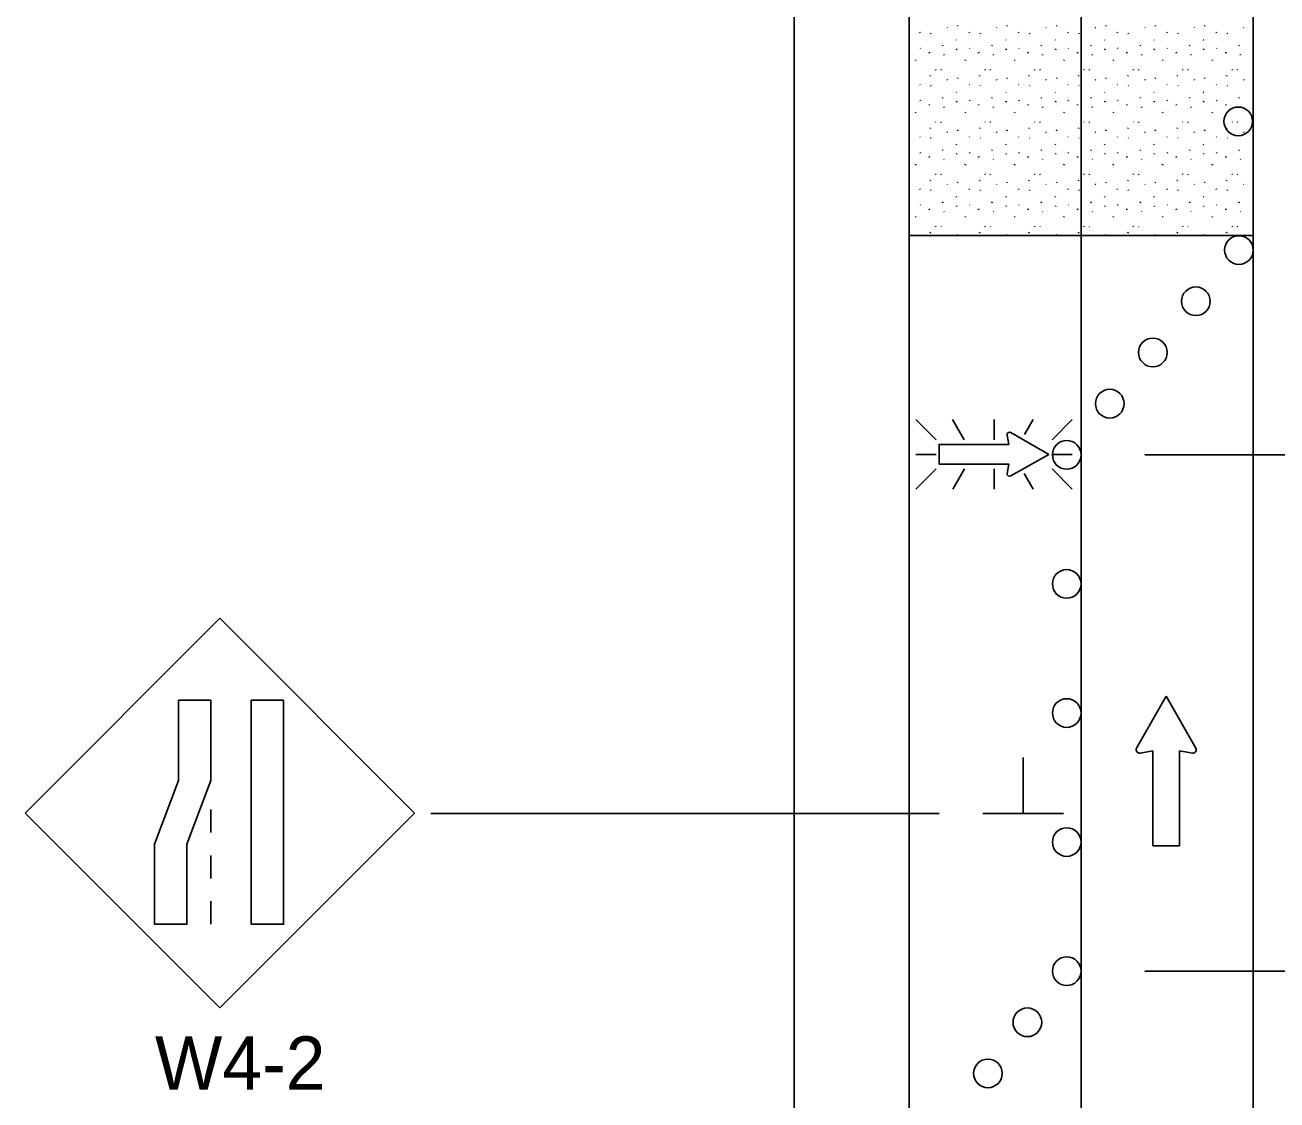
# Model space of a CAD drawing. Extents: x 16794 to 19504, y 7009 to 8243.
# Drawn here: x 17909.1 to 18083.7, y 7860.1 to 8010 of the extents above; entities that cross this region are included whole.
import ezdxf

# ---------------------------------------------------------------- set-up
doc = ezdxf.new("R2010")
doc.units = 0
for name, color, linetype in [('ALI_LEGAL_EX', 7, 'Continuous'), ('MT_SCRATCH_LEVEL_A', 7, 'Continuous'), ('MT_SCRATCH_LEVEL_E', 7, 'Continuous'), ('PAVT_EDGE_EX', 7, 'Continuous'), ('TRAFFIC_SIGNS_PR', 7, 'Continuous'), ('TYPICAL_TEXT_DIMEN_PR', 7, 'Continuous')]:
    doc.layers.add(name, color=color, linetype=linetype)

msp = doc.modelspace()

# ---------------------------------------------------------------- linework, layer by layer
at = {"layer": 'ALI_LEGAL_EX'}
for p, q in [((18056.37, 8191.42), (18056.37, 7362.23)), ((18080.37, 8191.42), (18080.37, 7362.23)), ((18080.37, 8191.42), (18080.37, 7362.23))]:
    msp.add_line(p, q, dxfattribs=at)
for points in [[(18056.37, 7991.42), (18056.37, 7966.42)], [(18080.37, 7991.42), (18080.37, 7980.06)], [(18056.37, 7891.42), (18056.37, 7880.22)], [(18080.37, 7891.42), (18080.37, 7866.42)]]:
    msp.add_lwpolyline(points, dxfattribs=at)
at = {"layer": 'MT_SCRATCH_LEVEL_A'}
msp.add_line((18080.37, 7980.62), (18032.37, 7980.62), dxfattribs=at)
at = {"layer": 'MT_SCRATCH_LEVEL_E'}
for p, q in [((18068.21, 7916.38), (18064.1, 7909.14)), ((18072.36, 7909.14), (18068.21, 7916.38)), ((18064.58, 7908.46), (18066.36, 7908.77)), ((18066.36, 7908.77), (18066.36, 7895.52)), ((18070.1, 7895.52), (18070.1, 7908.77)), ((18070.1, 7908.77), (18071.88, 7908.46)), ((18066.36, 7895.52), (18070.1, 7895.52))]:
    msp.add_line(p, q, dxfattribs=at)
for centre, start, end in [((18064.51, 7908.92), 150.4248, 279.9638), ((18071.95, 7908.92), 260.0362, 29.7731)]:
    msp.add_arc(centre, 0.463, start, end, dxfattribs=at)
at = {"layer": 'PAVT_EDGE_EX'}
for p, q in [((18016.37, 8214.7), (18016.37, 7554.34)), ((18032.37, 8214.7), (18032.37, 7554.34)), ((18032.37, 8010.04), (18032.37, 7980.62)), ((18037.68, 8009.67), (18037.73, 8009.59)), ((18039.13, 8009.82), (18039.18, 8009.94)), ((18044.57, 8009.67), (18044.62, 8009.59)), ((18046.02, 8009.82), (18046.07, 8009.94)), ((18051.46, 8009.67), (18051.51, 8009.59)), ((18052.91, 8009.82), (18052.96, 8009.94)), ((18058.34, 8009.67), (18058.4, 8009.59)), ((18059.79, 8009.82), (18059.85, 8009.94)), ((18065.23, 8009.67), (18065.28, 8009.59)), ((18066.68, 8009.82), (18066.73, 8009.94)), ((18072.12, 8009.67), (18072.17, 8009.59)), ((18073.57, 8009.82), (18073.62, 8009.94)), ((18079.01, 8009.67), (18079.06, 8009.59)), ((18033.86, 8008.99), (18033.91, 8008.92)), ((18035.39, 8008.85), (18035.44, 8008.78)), ((18038.96, 8007.93), (18039.01, 8007.86)), ((18040.75, 8008.99), (18040.8, 8008.92)), ((18042.28, 8008.85), (18042.33, 8008.78)), ((18045.85, 8007.93), (18045.9, 8007.86)), ((18047.64, 8008.99), (18047.69, 8008.92)), ((18049.17, 8008.85), (18049.22, 8008.78)), ((18052.73, 8007.93), (18052.79, 8007.86)), ((18054.53, 8008.99), (18054.58, 8008.92)), ((18056.06, 8008.85), (18056.11, 8008.78)), ((18059.62, 8007.93), (18059.67, 8007.86)), ((18061.41, 8008.99), (18061.46, 8008.92)), ((18062.94, 8008.85), (18062.99, 8008.78)), ((18066.51, 8007.93), (18066.56, 8007.86)), ((18068.3, 8008.99), (18068.35, 8008.92)), ((18069.83, 8008.85), (18069.88, 8008.78)), ((18073.4, 8007.93), (18073.45, 8007.86)), ((18075.19, 8008.99), (18075.24, 8008.92)), ((18076.72, 8008.85), (18076.77, 8008.78)), ((18080.28, 8007.93), (18080.34, 8007.86)), ((18033.91, 8006.78), (18033.96, 8006.71)), ((18035.19, 8006.21), (18035.21, 8006.09)), ((18037.03, 8007.07), (18037.08, 8007.18)), ((18037.22, 8005.86), (18037.27, 8005.79)), ((18039, 8006.53), (18039.05, 8006.65)), ((18040.8, 8006.78), (18040.85, 8006.71)), ((18042.08, 8006.21), (18042.09, 8006.09)), ((18043.92, 8007.07), (18043.97, 8007.18)), ((18044.11, 8005.86), (18044.16, 8005.79)), ((18045.89, 8006.53), (18045.94, 8006.65)), ((18047.69, 8006.78), (18047.74, 8006.71)), ((18048.97, 8006.21), (18048.98, 8006.09)), ((18050.81, 8007.07), (18050.86, 8007.18)), ((18051, 8005.86), (18051.05, 8005.79)), ((18052.78, 8006.53), (18052.83, 8006.65)), ((18054.57, 8006.78), (18054.62, 8006.71)), ((18055.85, 8006.21), (18055.87, 8006.09)), ((18057.7, 8007.07), (18057.75, 8007.18)), ((18057.89, 8005.86), (18057.94, 8005.79)), ((18059.66, 8006.53), (18059.72, 8006.65)), ((18061.46, 8006.78), (18061.51, 8006.71)), ((18062.74, 8006.21), (18062.76, 8006.09)), ((18064.58, 8007.07), (18064.64, 8007.18)), ((18064.77, 8005.86), (18064.82, 8005.79)), ((18066.55, 8006.53), (18066.6, 8006.65)), ((18068.35, 8006.78), (18068.4, 8006.71)), ((18069.63, 8006.21), (18069.64, 8006.09)), ((18071.47, 8007.07), (18071.52, 8007.18)), ((18071.66, 8005.86), (18071.71, 8005.79)), ((18073.44, 8006.53), (18073.49, 8006.65)), ((18075.24, 8006.78), (18075.29, 8006.71)), ((18076.52, 8006.21), (18076.53, 8006.09)), ((18078.36, 8007.07), (18078.41, 8007.18)), ((18078.55, 8005.86), (18078.6, 8005.79)), ((18080.33, 8006.53), (18080.37, 8006.62)), ((18033.29, 8005.03), (18033.34, 8005.15)), ((18040.18, 8005.03), (18040.23, 8005.15)), ((18047.07, 8005.03), (18047.12, 8005.15)), ((18053.96, 8005.03), (18054.01, 8005.15)), ((18060.84, 8005.03), (18060.89, 8005.15)), ((18067.73, 8005.03), (18067.78, 8005.15)), ((18074.62, 8005.03), (18074.67, 8005.15)), ((18035.31, 8002.84), (18035.36, 8002.95)), ((18036.08, 8003.8), (18036.13, 8003.72)), ((18036.81, 8003.77), (18036.87, 8003.69)), ((18037.68, 8002.39), (18037.73, 8002.31)), ((18039.13, 8002.54), (18039.18, 8002.65)), ((18042.2, 8002.84), (18042.25, 8002.95)), ((18042.96, 8003.8), (18043.01, 8003.72)), ((18043.7, 8003.77), (18043.75, 8003.69)), ((18044.57, 8002.39), (18044.62, 8002.31)), ((18046.02, 8002.54), (18046.07, 8002.65)), ((18049.09, 8002.84), (18049.14, 8002.95)), ((18049.85, 8003.8), (18049.9, 8003.72)), ((18050.59, 8003.77), (18050.64, 8003.69)), ((18051.46, 8002.39), (18051.51, 8002.31)), ((18052.91, 8002.54), (18052.96, 8002.65)), ((18055.98, 8002.84), (18056.03, 8002.95)), ((18056.74, 8003.8), (18056.79, 8003.72)), ((18057.48, 8003.77), (18057.53, 8003.69)), ((18058.34, 8002.39), (18058.4, 8002.31)), ((18059.79, 8002.54), (18059.85, 8002.65)), ((18062.86, 8002.84), (18062.91, 8002.95)), ((18063.63, 8003.8), (18063.68, 8003.72)), ((18064.36, 8003.77), (18064.42, 8003.69)), ((18065.23, 8002.39), (18065.28, 8002.31)), ((18066.68, 8002.54), (18066.73, 8002.65)), ((18069.75, 8002.84), (18069.8, 8002.95)), ((18070.51, 8003.8), (18070.56, 8003.72)), ((18071.25, 8003.77), (18071.3, 8003.69)), ((18072.12, 8002.39), (18072.17, 8002.31)), ((18073.57, 8002.54), (18073.62, 8002.65)), ((18076.64, 8002.84), (18076.69, 8002.95)), ((18077.4, 8003.8), (18077.45, 8003.72)), ((18078.14, 8003.77), (18078.19, 8003.69)), ((18079.01, 8002.39), (18079.06, 8002.31)), ((18033.86, 8001.71), (18033.91, 8001.63)), ((18035.39, 8001.57), (18035.44, 8001.49)), ((18038.96, 8000.65), (18039.01, 8000.57)), ((18040.75, 8001.71), (18040.8, 8001.63)), ((18042.28, 8001.57), (18042.33, 8001.49)), ((18045.85, 8000.65), (18045.9, 8000.57)), ((18047.64, 8001.71), (18047.69, 8001.63)), ((18049.17, 8001.57), (18049.22, 8001.49)), ((18052.73, 8000.65), (18052.79, 8000.57)), ((18054.53, 8001.71), (18054.58, 8001.63)), ((18056.06, 8001.57), (18056.11, 8001.49)), ((18059.62, 8000.65), (18059.67, 8000.57)), ((18061.41, 8001.71), (18061.46, 8001.63)), ((18062.94, 8001.57), (18062.99, 8001.49)), ((18066.51, 8000.65), (18066.56, 8000.57)), ((18068.3, 8001.71), (18068.35, 8001.63)), ((18069.83, 8001.57), (18069.88, 8001.49)), ((18073.4, 8000.65), (18073.45, 8000.57)), ((18075.19, 8001.71), (18075.24, 8001.63)), ((18076.72, 8001.57), (18076.77, 8001.49)), ((18080.28, 8000.65), (18080.34, 8000.57)), ((18033.91, 7999.5), (18033.96, 7999.42)), ((18035.19, 7998.92), (18035.21, 7998.81)), ((18037.03, 7999.78), (18037.08, 7999.9)), ((18039, 7999.25), (18039.05, 7999.37)), ((18040.8, 7999.5), (18040.85, 7999.42)), ((18042.08, 7998.92), (18042.09, 7998.81)), ((18043.92, 7999.78), (18043.97, 7999.9)), ((18045.89, 7999.25), (18045.94, 7999.37)), ((18047.69, 7999.5), (18047.74, 7999.42)), ((18048.97, 7998.92), (18048.98, 7998.81)), ((18050.81, 7999.78), (18050.86, 7999.9)), ((18052.78, 7999.25), (18052.83, 7999.37)), ((18054.57, 7999.5), (18054.62, 7999.42)), ((18055.85, 7998.92), (18055.87, 7998.81)), ((18057.7, 7999.78), (18057.75, 7999.9)), ((18059.66, 7999.25), (18059.72, 7999.37)), ((18061.46, 7999.5), (18061.51, 7999.42)), ((18062.74, 7998.92), (18062.76, 7998.81)), ((18064.58, 7999.78), (18064.64, 7999.9)), ((18066.55, 7999.25), (18066.6, 7999.37)), ((18068.35, 7999.5), (18068.4, 7999.42)), ((18069.63, 7998.92), (18069.64, 7998.81)), ((18071.47, 7999.78), (18071.52, 7999.9)), ((18073.44, 7999.25), (18073.49, 7999.37)), ((18075.24, 7999.5), (18075.29, 7999.42)), ((18076.52, 7998.92), (18076.53, 7998.81)), ((18078.36, 7999.78), (18078.41, 7999.9)), ((18080.33, 7999.25), (18080.37, 7999.34)), ((18033.29, 7997.75), (18033.34, 7997.86)), ((18037.22, 7998.58), (18037.27, 7998.5)), ((18040.18, 7997.75), (18040.23, 7997.86)), ((18044.11, 7998.58), (18044.16, 7998.5)), ((18047.07, 7997.75), (18047.12, 7997.86)), ((18051, 7998.58), (18051.05, 7998.5)), ((18053.96, 7997.75), (18054.01, 7997.86)), ((18057.89, 7998.58), (18057.94, 7998.5)), ((18060.84, 7997.75), (18060.89, 7997.86)), ((18064.77, 7998.58), (18064.82, 7998.5)), ((18067.73, 7997.75), (18067.78, 7997.86)), ((18071.66, 7998.58), (18071.71, 7998.5)), ((18074.62, 7997.75), (18074.67, 7997.86)), ((18078.55, 7998.58), (18078.6, 7998.5)), ((18035.31, 7995.55), (18035.36, 7995.67)), ((18036.08, 7996.51), (18036.13, 7996.43)), ((18036.81, 7996.48), (18036.87, 7996.4)), ((18039.13, 7995.25), (18039.18, 7995.37)), ((18042.2, 7995.55), (18042.25, 7995.67)), ((18042.96, 7996.51), (18043.01, 7996.43)), ((18043.7, 7996.48), (18043.75, 7996.4)), ((18046.02, 7995.25), (18046.07, 7995.37)), ((18049.09, 7995.55), (18049.14, 7995.67)), ((18049.85, 7996.51), (18049.9, 7996.43)), ((18050.59, 7996.48), (18050.64, 7996.4)), ((18052.91, 7995.25), (18052.96, 7995.37)), ((18055.98, 7995.55), (18056.03, 7995.67)), ((18056.74, 7996.51), (18056.79, 7996.43)), ((18057.48, 7996.48), (18057.53, 7996.4)), ((18059.79, 7995.25), (18059.85, 7995.37)), ((18062.86, 7995.55), (18062.91, 7995.67)), ((18063.63, 7996.51), (18063.68, 7996.43)), ((18064.36, 7996.48), (18064.42, 7996.4)), ((18066.68, 7995.25), (18066.73, 7995.37)), ((18069.75, 7995.55), (18069.8, 7995.67)), ((18070.51, 7996.51), (18070.56, 7996.43)), ((18071.25, 7996.48), (18071.3, 7996.4)), ((18073.57, 7995.25), (18073.62, 7995.37)), ((18076.64, 7995.55), (18076.69, 7995.67)), ((18077.4, 7996.51), (18077.45, 7996.43)), ((18078.14, 7996.48), (18078.19, 7996.4)), ((18033.86, 7994.42), (18033.91, 7994.35)), ((18035.39, 7994.28), (18035.44, 7994.21)), ((18037.68, 7995.1), (18037.73, 7995.02)), ((18040.75, 7994.42), (18040.8, 7994.35)), ((18042.28, 7994.28), (18042.33, 7994.21)), ((18044.57, 7995.1), (18044.62, 7995.02)), ((18047.64, 7994.42), (18047.69, 7994.35)), ((18049.17, 7994.28), (18049.22, 7994.21)), ((18051.46, 7995.1), (18051.51, 7995.02)), ((18054.53, 7994.42), (18054.58, 7994.35)), ((18056.06, 7994.28), (18056.11, 7994.21)), ((18058.34, 7995.1), (18058.4, 7995.02)), ((18061.41, 7994.42), (18061.46, 7994.35)), ((18062.94, 7994.28), (18062.99, 7994.21)), ((18065.23, 7995.1), (18065.28, 7995.02)), ((18068.3, 7994.42), (18068.35, 7994.35)), ((18069.83, 7994.28), (18069.88, 7994.21)), ((18072.12, 7995.1), (18072.17, 7995.02)), ((18075.19, 7994.42), (18075.24, 7994.35)), ((18076.72, 7994.28), (18076.77, 7994.21)), ((18079.01, 7995.1), (18079.06, 7995.02)), ((18033.91, 7992.22), (18033.96, 7992.14)), ((18037.03, 7992.49), (18037.08, 7992.61)), ((18038.96, 7993.36), (18039.01, 7993.29)), ((18039, 7991.96), (18039.05, 7992.08)), ((18040.8, 7992.22), (18040.85, 7992.14)), ((18043.92, 7992.49), (18043.97, 7992.61)), ((18045.85, 7993.36), (18045.9, 7993.29)), ((18045.89, 7991.96), (18045.94, 7992.08)), ((18047.69, 7992.22), (18047.74, 7992.14)), ((18050.81, 7992.49), (18050.86, 7992.61)), ((18052.73, 7993.36), (18052.79, 7993.29)), ((18052.78, 7991.96), (18052.83, 7992.08)), ((18054.57, 7992.22), (18054.62, 7992.14)), ((18057.7, 7992.49), (18057.75, 7992.61)), ((18059.62, 7993.36), (18059.67, 7993.29)), ((18059.66, 7991.96), (18059.72, 7992.08)), ((18061.46, 7992.22), (18061.51, 7992.14)), ((18064.58, 7992.49), (18064.64, 7992.61)), ((18066.51, 7993.36), (18066.56, 7993.29)), ((18066.55, 7991.96), (18066.6, 7992.08)), ((18068.35, 7992.22), (18068.4, 7992.14)), ((18071.47, 7992.49), (18071.52, 7992.61)), ((18073.4, 7993.36), (18073.45, 7993.29)), ((18073.44, 7991.96), (18073.49, 7992.08)), ((18075.24, 7992.22), (18075.29, 7992.14)), ((18078.36, 7992.49), (18078.41, 7992.61)), ((18080.28, 7993.36), (18080.34, 7993.29)), ((18080.33, 7991.96), (18080.37, 7992.05)), ((18033.29, 7990.46), (18033.34, 7990.58)), ((18035.19, 7991.64), (18035.21, 7991.52)), ((18037.22, 7991.3), (18037.27, 7991.22)), ((18040.18, 7990.46), (18040.23, 7990.58)), ((18042.08, 7991.64), (18042.09, 7991.52)), ((18044.11, 7991.3), (18044.16, 7991.22)), ((18047.07, 7990.46), (18047.12, 7990.58)), ((18048.97, 7991.64), (18048.98, 7991.52)), ((18051, 7991.3), (18051.05, 7991.22)), ((18053.96, 7990.46), (18054.01, 7990.58)), ((18055.85, 7991.64), (18055.87, 7991.52)), ((18057.89, 7991.3), (18057.94, 7991.22)), ((18060.84, 7990.46), (18060.89, 7990.58)), ((18062.74, 7991.64), (18062.76, 7991.52)), ((18064.77, 7991.3), (18064.82, 7991.22)), ((18067.73, 7990.46), (18067.78, 7990.58)), ((18069.63, 7991.64), (18069.64, 7991.52)), ((18071.66, 7991.3), (18071.71, 7991.22)), ((18074.62, 7990.46), (18074.67, 7990.58)), ((18076.52, 7991.64), (18076.53, 7991.52)), ((18078.55, 7991.3), (18078.6, 7991.22)), ((18035.31, 7988.27), (18035.36, 7988.38)), ((18036.08, 7989.23), (18036.13, 7989.15)), ((18036.81, 7989.2), (18036.87, 7989.12)), ((18042.2, 7988.27), (18042.25, 7988.38)), ((18042.96, 7989.23), (18043.01, 7989.15)), ((18043.7, 7989.2), (18043.75, 7989.12)), ((18049.09, 7988.27), (18049.14, 7988.38)), ((18049.85, 7989.23), (18049.9, 7989.15)), ((18050.59, 7989.2), (18050.64, 7989.12)), ((18055.98, 7988.27), (18056.03, 7988.38)), ((18056.74, 7989.23), (18056.79, 7989.15)), ((18057.48, 7989.2), (18057.53, 7989.12)), ((18062.86, 7988.27), (18062.91, 7988.38)), ((18063.63, 7989.23), (18063.68, 7989.15)), ((18064.36, 7989.2), (18064.42, 7989.12)), ((18069.75, 7988.27), (18069.8, 7988.38)), ((18070.51, 7989.23), (18070.56, 7989.15)), ((18071.25, 7989.2), (18071.3, 7989.12)), ((18076.64, 7988.27), (18076.69, 7988.38)), ((18077.4, 7989.23), (18077.45, 7989.15)), ((18078.14, 7989.2), (18078.19, 7989.12)), ((18033.86, 7987.14), (18033.91, 7987.06)), ((18035.39, 7987), (18035.44, 7986.92)), ((18037.68, 7987.82), (18037.73, 7987.74)), ((18039.13, 7987.97), (18039.18, 7988.09)), ((18040.75, 7987.14), (18040.8, 7987.06)), ((18042.28, 7987), (18042.33, 7986.92)), ((18044.57, 7987.82), (18044.62, 7987.74)), ((18046.02, 7987.97), (18046.07, 7988.09)), ((18047.64, 7987.14), (18047.69, 7987.06)), ((18049.17, 7987), (18049.22, 7986.92)), ((18051.46, 7987.82), (18051.51, 7987.74)), ((18052.91, 7987.97), (18052.96, 7988.09)), ((18054.53, 7987.14), (18054.58, 7987.06)), ((18056.06, 7987), (18056.11, 7986.92)), ((18058.34, 7987.82), (18058.4, 7987.74)), ((18059.79, 7987.97), (18059.85, 7988.09)), ((18061.41, 7987.14), (18061.46, 7987.06)), ((18062.94, 7987), (18062.99, 7986.92)), ((18065.23, 7987.82), (18065.28, 7987.74)), ((18066.68, 7987.97), (18066.73, 7988.09)), ((18068.3, 7987.14), (18068.35, 7987.06)), ((18069.83, 7987), (18069.88, 7986.92)), ((18072.12, 7987.82), (18072.17, 7987.74)), ((18073.57, 7987.97), (18073.62, 7988.09)), ((18075.19, 7987.14), (18075.24, 7987.06)), ((18076.72, 7987), (18076.77, 7986.92)), ((18079.01, 7987.82), (18079.06, 7987.74)), ((18033.91, 7984.93), (18033.96, 7984.85)), ((18037.03, 7985.21), (18037.08, 7985.33)), ((18038.96, 7986.08), (18039.01, 7986)), ((18040.8, 7984.93), (18040.85, 7984.85)), ((18043.92, 7985.21), (18043.97, 7985.33)), ((18045.85, 7986.08), (18045.9, 7986)), ((18047.69, 7984.93), (18047.74, 7984.85)), ((18050.81, 7985.21), (18050.86, 7985.33)), ((18052.73, 7986.08), (18052.79, 7986)), ((18054.57, 7984.93), (18054.62, 7984.85)), ((18057.7, 7985.21), (18057.75, 7985.33)), ((18059.62, 7986.08), (18059.67, 7986)), ((18061.46, 7984.93), (18061.51, 7984.85)), ((18064.58, 7985.21), (18064.64, 7985.33)), ((18066.51, 7986.08), (18066.56, 7986)), ((18068.35, 7984.93), (18068.4, 7984.85)), ((18071.47, 7985.21), (18071.52, 7985.33)), ((18073.4, 7986.08), (18073.45, 7986)), ((18075.24, 7984.93), (18075.29, 7984.85)), ((18078.36, 7985.21), (18078.41, 7985.33)), ((18080.28, 7986.08), (18080.34, 7986)), ((18033.29, 7983.18), (18033.34, 7983.29)), ((18035.19, 7984.35), (18035.21, 7984.24)), ((18037.22, 7984.01), (18037.27, 7983.93)), ((18039, 7984.68), (18039.05, 7984.8)), ((18040.18, 7983.18), (18040.23, 7983.29)), ((18042.08, 7984.35), (18042.09, 7984.24)), ((18044.11, 7984.01), (18044.16, 7983.93)), ((18045.89, 7984.68), (18045.94, 7984.8)), ((18047.07, 7983.18), (18047.12, 7983.29)), ((18048.97, 7984.35), (18048.98, 7984.24)), ((18051, 7984.01), (18051.05, 7983.93)), ((18052.78, 7984.68), (18052.83, 7984.8)), ((18053.96, 7983.18), (18054.01, 7983.29)), ((18055.85, 7984.35), (18055.87, 7984.24)), ((18057.89, 7984.01), (18057.94, 7983.93)), ((18059.66, 7984.68), (18059.72, 7984.8)), ((18060.84, 7983.18), (18060.89, 7983.29)), ((18062.74, 7984.35), (18062.76, 7984.24)), ((18064.77, 7984.01), (18064.82, 7983.93)), ((18066.55, 7984.68), (18066.6, 7984.8)), ((18067.73, 7983.18), (18067.78, 7983.29)), ((18069.63, 7984.35), (18069.64, 7984.24)), ((18071.66, 7984.01), (18071.71, 7983.93)), ((18073.44, 7984.68), (18073.49, 7984.8)), ((18074.62, 7983.18), (18074.67, 7983.29)), ((18076.52, 7984.35), (18076.53, 7984.24)), ((18078.55, 7984.01), (18078.6, 7983.93)), ((18080.33, 7984.68), (18080.37, 7984.77)), ((18036.08, 7981.94), (18036.13, 7981.86)), ((18036.81, 7981.91), (18036.87, 7981.83)), ((18042.96, 7981.94), (18043.01, 7981.86)), ((18043.7, 7981.91), (18043.75, 7981.83)), ((18049.85, 7981.94), (18049.9, 7981.86)), ((18050.59, 7981.91), (18050.64, 7981.83)), ((18056.74, 7981.94), (18056.79, 7981.86)), ((18057.48, 7981.91), (18057.53, 7981.83)), ((18063.63, 7981.94), (18063.68, 7981.86)), ((18064.36, 7981.91), (18064.42, 7981.83)), ((18070.51, 7981.94), (18070.56, 7981.86)), ((18071.25, 7981.91), (18071.3, 7981.83)), ((18077.4, 7981.94), (18077.45, 7981.86)), ((18078.14, 7981.91), (18078.19, 7981.83)), ((18032.37, 7980.62), (18080.37, 7980.62)), ((18035.31, 7980.98), (18035.36, 7981.1)), ((18039.13, 7980.68), (18039.18, 7980.8)), ((18042.2, 7980.98), (18042.25, 7981.1)), ((18046.02, 7980.68), (18046.07, 7980.8)), ((18049.09, 7980.98), (18049.14, 7981.1)), ((18052.91, 7980.68), (18052.96, 7980.8)), ((18055.98, 7980.98), (18056.03, 7981.1)), ((18059.79, 7980.68), (18059.85, 7980.8)), ((18062.86, 7980.98), (18062.91, 7981.1)), ((18066.68, 7980.68), (18066.73, 7980.8)), ((18069.75, 7980.98), (18069.8, 7981.1)), ((18073.57, 7980.68), (18073.62, 7980.8)), ((18076.64, 7980.98), (18076.69, 7981.1))]:
    msp.add_line(p, q, dxfattribs=at)
at = {"layer": 'TRAFFIC_SIGNS_PR'}
for p, q in [((18036.14, 7952.15), (18033.32, 7954.98)), ((18038.44, 7954.98), (18040.06, 7952.15)), ((18044.23, 7952.15), (18044.23, 7954.98)), ((18049.69, 7954.98), (18048.49, 7952.88)), ((18055.13, 7954.97), (18052.31, 7952.15)), ((18036.14, 7950.12), (18033.32, 7950.12)), ((18052.31, 7950.12), (18055.13, 7950.12)), ((18036.14, 7948.09), (18033.32, 7945.27)), ((18040.09, 7948.09), (18038.46, 7945.27)), ((18044.23, 7948.09), (18044.23, 7945.27)), ((18048.41, 7947.46), (18049.67, 7945.27)), ((18055.13, 7945.27), (18052.31, 7948.09)), ((17936.29, 7927.26), (17909.14, 7900.1)), ((17963.44, 7900.1), (17936.29, 7927.26)), ((17909.14, 7900.1), (17936.29, 7872.95)), ((17935.04, 7900.59), (17935.04, 7897.39)), ((17936.29, 7872.95), (17963.44, 7900.1)), ((17935.04, 7894.19), (17935.04, 7890.99)), ((17935.04, 7887.79), (17935.04, 7884.59))]:
    msp.add_line(p, q, dxfattribs=at)
for points in [[(18046.05, 7952.81), (18046.28, 7951.51), (18036.56, 7951.51), (18036.56, 7948.77), (18046.28, 7948.77), (18046.05, 7947.46)], [(18046.55, 7947.11), (18051.86, 7950.12), (18046.55, 7953.16)]]:
    msp.add_lwpolyline(points, dxfattribs=at)
for points in [[(17935.04, 7915.84), (17935.04, 7904.66), (17931.7, 7895.78), (17931.7, 7884.59), (17927.2, 7884.59), (17927.2, 7895.78), (17930.55, 7904.66), (17930.55, 7915.84)], [(17945.18, 7915.84), (17945.18, 7884.59), (17940.68, 7884.59), (17940.68, 7915.84)]]:
    msp.add_lwpolyline(points, close=True, dxfattribs=at)
for centre in [(18078.27, 7996.56), (18078.36, 7978.61), (18072.36, 7971.47), (18066.36, 7964.33), (18060.36, 7957.19), (18054.36, 7950.05), (18054.36, 7932.05), (18054.36, 7914.05), (18054.36, 7896.05), (18054.36, 7878.05), (18048.87, 7870.92), (18043.37, 7863.79)]:
    msp.add_circle(centre, 2, dxfattribs=at)
for centre, start, end in [((18046.39, 7952.86), 61.4833, 189.9593), ((18046.39, 7947.41), 170.7308, 298.8916)]:
    msp.add_arc(centre, 0.341, start, end, dxfattribs=at)
at = {"layer": 'TYPICAL_TEXT_DIMEN_PR'}
for p, q in [((18196.41, 7950.05), (18065.26, 7950.05)), ((18048.29, 7900.05), (18048.29, 7907.84)), ((17965.69, 7900.05), (18036.56, 7900.05)), ((18053.92, 7900.05), (18042.67, 7900.05)), ((18065.26, 7878.05), (18196.41, 7878.05))]:
    msp.add_line(p, q, dxfattribs=at)

# ---------------------------------------------------------------- texts
at = {"layer": 'TRAFFIC_SIGNS_PR'}
msp.add_text('W4-2', height=7.44, dxfattribs=at).set_placement((17927.25, 7861.51))

doc.saveas('drawing.dxf')
